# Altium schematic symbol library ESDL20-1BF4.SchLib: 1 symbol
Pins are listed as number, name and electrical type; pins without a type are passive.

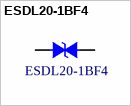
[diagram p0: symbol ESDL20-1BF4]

## ESDL20-1BF4
designator D?
footprint ST_0201B_CSP_ap
pins: 1, 2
